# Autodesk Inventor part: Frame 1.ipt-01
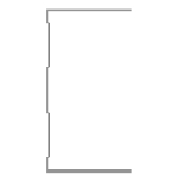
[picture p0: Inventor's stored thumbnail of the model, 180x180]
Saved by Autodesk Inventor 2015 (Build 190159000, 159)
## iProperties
IsCustomPart: 1
Created: 2015-04
Part Number: Frame 1.ipt-01
Material: Aluminum 6061
Description: Kévin Novo
Document SubType Name: Modeling
Standard: Kevin
Designer: suporte
Standards Organization: Kevin
Language: en-US
Size Designation: (Unnamed 1)
Categories: <MemberInstance><Categories><Category DisplayName="Structural Shapes" InternalName="089c4875-fa83-4c05-b084-43b9cc11f5ed" Mnemonic="GRDR"><CategoryParameter Dis
Density: 2.7 g/cm^3
Appearance: Aluminum - Flat
_CCFamilyMember: 1
_CCFamilyDisplayName: Kévin - Kévin Novo
_FrameMemberDoc: Frame Member File
_Version: 15.0.0
_GetPNFromCC: 1
G_L: 1150,000 mm
G_W: 50,000 mm
G_H: 75,000 mm
+3D70875A-E5A9-4FDA-85E3-2CF6FFD64956+CUTDETAIL1: Cut
+E4C8F863-C9A0-4110-9EB7-EA6FC54E2E86+CUTDETAIL2: Cut
Author: suporte
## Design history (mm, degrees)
node "Start Plane"
node "End Plane"
sketch "Sketch"
  geometry: L1 (24.7, 37.5)-(24.7, 36.9); L2 (24.7, 36.9)-(-24.7, 36.9); L3 (-24.7, -36.9)-(24.7, -36.9); L4 (24.7, -36.9)-(24.7, -37.5); L5 (24.7, -37.5)-(-25.3, -37.5); L6 (-25.3, 37.5)-(24.7, 37.5); L7 (-24.7, 36.9)-(-24.7, 31.9); L8 (-24.7, 31.9)-(-23.3, 30.5); L9 (-23.3, 30.5)-(-23.3, 10.934); L10 (-23.3, 10.934)-(-24.7, 9.534); L11 (-24.7, 9.534)-(-24.7, -9.534); L12 (-24.7, -9.534)-(-23.3, -10.934); L13 (-23.3, -10.934)-(-23.3, -30.5); L14 (-23.3, -30.5)-(-24.7, -31.9); L15 (-24.7, -31.9)-(-24.7, -36.9); L16 (-25.3, -37.5)-(-25.3, -31.651); L17 (-25.3, -31.651)-(-23.9, -30.251); L18 (-23.9, -30.251)-(-23.9, -11.183); L19 (-23.9, -11.183)-(-25.3, -9.783); L20 (-25.3, -9.783)-(-25.3, 9.783); L21 (-25.3, 9.783)-(-23.9, 11.183); L22 (-23.9, 11.183)-(-23.9, 30.251); L23 (-23.9, 30.251)-(-25.3, 31.651); L24 (-25.3, 31.651)-(-25.3, 37.5); L25 (-25.3, 0)-(30.37, 0); 3 further points
  constraints: 50 end point, 10 point on line, 9 parallel, 5 perpendicular, 4 equal length, 3 midpoint, 3 vertical, 2 vertical alignment, 1 collinear, 1 horizontal, 1 horizontal alignment
  dimensions: "d3" = 0.6 distance of L1.start L1.end (= d6); "d5" = 75 distance between parallel lines of L5 L6; "d6" = 0.6 distance between parallel lines of L24 L7 (= d8); "d7" = 0.6 distance between parallel lines of L8 L23 (= d8); "d8" = 0.6 distance between parallel lines of L22 L9 (= d12); "Espessura" = 0.6 distance between parallel lines of L17 L14; "d10" = 0.6 distance between parallel lines of L13 L18 (= Espessura); "d11" = 0.6 distance between parallel lines of L12 L19 (= Espessura); "d12" = 0.6 distance between parallel lines of L21 L10 (= d11); "d13" = 5 distance of L2.end L7.end; "d15" = 135 deg angle of L9 L8; "d16" = 2 distance between parallel lines of L24 L9; "d17" = 50 distance of L6.start L1.start
extrude "Body" join sketch "Sketch" stored distance "d24" = 0.13; taper "d25" = 0 deg
node "Driven Length"
  sketch "Sketch10"
    geometry: L1 (0, 0)-(10, 0) reference
    constraints: 2 end point, 1 horizontal
  workplane "Work Plane7"
  sketch "Sketch11"
    geometry: L1 (-2, 37.5)-(12, 37.5) reference; L2 (-2, 1187.5)-(12, 1187.5) reference
    dimensions: "d27" = 1150 distance between parallel lines of L1 L2 (derived)
workplane "Work Plane8"
split "Split1"
workplane "Work Plane9"
split "Split2"
body "Solid1"
other parameters: "G_OFFSET_START" = -37.5 [user parameter; used in 1 equation term], "G_OFFSET_END" = -12.5 [user parameter; used in 1 equation term], "d22" = 37.5 (= -G_OFFSET_START), "d23" = 1187.5 (= tamanho + G_OFFSET_END), "G_L" = 1150 (= d27) [user parameter], "d34" = 90 deg
